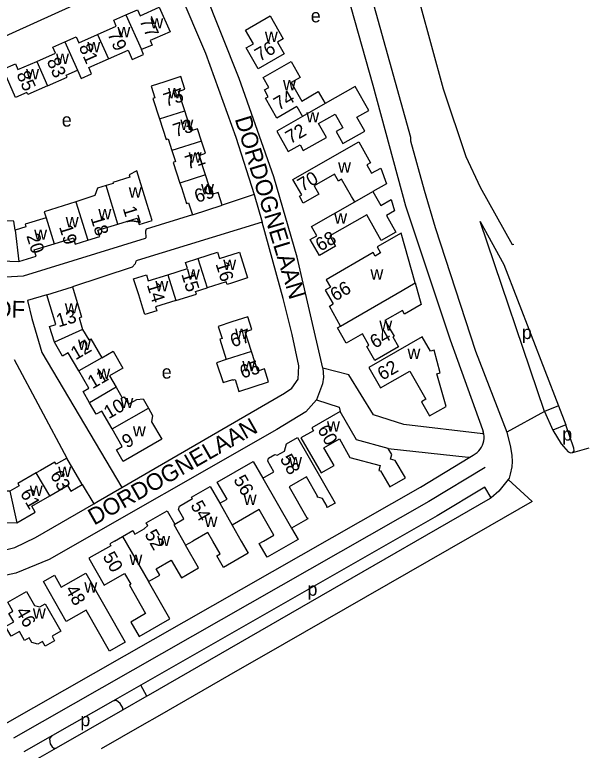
# Model space of a CAD drawing. Extents: x 157768 to 159790, y 387230 to 389604.
# Drawn here: x 159618.3 to 159790.2, y 387687.4 to 387907.4 of the extents above; entities that cross this region are included whole.
import ezdxf

# ---------------------------------------------------------------- set-up
doc = ezdxf.new("R2010")
doc.units = 0
for name, color, linetype in [('BLT_Basislijn', 7, 'Continuous'), ('BLT_Bebouwing', 7, 'Continuous'), ('BLT_Centroide', 7, 'Continuous'), ('BLT_Huisnummer', 7, 'Continuous'), ('BLT_Huisnummer_ tussenligend', 7, 'Continuous'), ('BLT_Onderverdeling_panden', 7, 'Continuous'), ('BLT_Straatnaam', 7, 'Continuous'), ('BLT_Vlakafsluiter', 7, 'Continuous')]:
    doc.layers.add(name, color=color, linetype=linetype)

msp = doc.modelspace()

# ---------------------------------------------------------------- linework, layer by layer
at = {"layer": 'BLT_Basislijn'}
for p, q in [((159689.89, 387853.69), (159680.34, 387850.45)), ((159689.89, 387853.69), (159692.33, 387845.34)), ((159692.33, 387845.34), (159654.95, 387833.88)), ((159698.63, 387822.58), (159692.33, 387845.34)), ((159776.83, 387788.74), (159757.5, 387845.57)), ((159654.54, 387833.72), (159654.31, 387832.93)), ((159654.95, 387833.88), (159654.54, 387833.72)), ((159653.42, 387831.93), (159635.54, 387825.99)), ((159654.31, 387832.93), (159653.42, 387831.93)), ((159627.9, 387823.61), (159622.13, 387821.9)), ((159701.32, 387811.81), (159698.63, 387822.58)), ((159622.13, 387821.9), (159623.39, 387816.59)), ((159623.39, 387816.59), (159626.45, 387806.4)), ((159703.31, 387802.36), (159701.32, 387811.81)), ((159626.45, 387806.4), (159650.38, 387766.04)), ((159618.18, 387804.29), (159633.89, 387774.8)), ((159703.1, 387798.44), (159703.31, 387802.36)), ((159701.25, 387795.73), (159703.1, 387798.44)), ((159650.38, 387766.04), (159699.05, 387794.25)), ((159699.05, 387794.25), (159701.25, 387795.73)), ((159780.97, 387790.46), (159783.16, 387784.76)), ((159776.83, 387788.74), (159779.26, 387783.11)), ((159783.16, 387784.76), (159779.26, 387783.11)), ((159758.37, 387782.06), (159758.63, 387781.96)), ((159758.63, 387781.96), (159758.47, 387782.64)), ((159765.55, 387782.51), (159766.67, 387778.05)), ((159730.05, 387777.68), (159753.92, 387775.06)), ((159753.92, 387775.06), (159754.42, 387775.06)), ((159754.42, 387775.06), (159755.48, 387775.7)), ((159638.49, 387766.86), (159641.92, 387761.15)), ((159655.99, 387706.92), (159647.62, 387702.15)), ((159657.83, 387703.59), (159655.99, 387706.92)), ((159647.62, 387702.15), (159629.57, 387691.87)), ((159657.83, 387703.59), (159650.54, 387699.41)), ((159650.54, 387699.41), (159630.74, 387688.08)), ((159661.61, 387697.84), (159656.3, 387694.79)), ((159656.3, 387694.79), (159644.16, 387687.83)), ((159629.57, 387691.87), (159621.02, 387687)), ((159630.74, 387688.08), (159622.98, 387683.64))]:
    msp.add_line(p, q, dxfattribs=at)
for points in [[(159692.84, 388081.49), (159706.76, 388031.4), (159708.11, 388025.69), (159746.51, 387885.2)], [(159720.03, 387930.6), (159736.67, 387870.75), (159736.74, 387869.7), (159740.78, 387854.95), (159744.13, 387843.74), (159756.15, 387806.81), (159765.55, 387782.51)], [(159713.96, 387928.53), (159716.64, 387917.56), (159725.48, 387886.3), (159735.17, 387850.25), (159748.57, 387810.22), (159758.29, 387783.31), (159758.47, 387782.64)], [(159593.73, 387893.44), (159598.42, 387893.3), (159661.18, 387921.83), (159663.45, 387921.58), (159665.84, 387918.02), (159667.43, 387914.68), (159675.33, 387895.95), (159684.44, 387870.81), (159689.89, 387853.69)], [(159710.46, 387801.68), (159702.78, 387834.9), (159695.78, 387858.95), (159685.49, 387888.37), (159674.92, 387914.97)], [(159746.51, 387885.2), (159753.28, 387864.96), (159757.5, 387855.82), (159767.09, 387838.67), (159767.58, 387838.81)], [(159671.47, 387847.59), (159657.67, 387843.31), (159657.41, 387842.64), (159657.56, 387840.64), (159657.34, 387840.48), (159620.87, 387829.25), (159606.86, 387828.46), (159591.66, 387828.05)], [(159757.5, 387845.57), (159764.67, 387832.74), (159780.97, 387790.46)], [(159710.46, 387801.68), (159710.63, 387798.96), (159710.4, 387797.04), (159708.54, 387792.2)], [(159758.37, 387782.06), (159734.73, 387784.83), (159725.65, 387787.71), (159718.29, 387799.71), (159710.46, 387801.68)], [(159708.54, 387792.2), (159705.37, 387788.65), (159696.74, 387783.35), (159628.58, 387744.46), (159618.61, 387740.41), (159614.41, 387739.52), (159607.82, 387739.2), (159553.26, 387740.56), (159549.08, 387741.46), (159546.02, 387742.49), (159541.79, 387744.82)], [(159708.54, 387792.2), (159715.35, 387789.99), (159715.66, 387788.79)], [(159780.97, 387790.46), (159776.83, 387788.74)], [(159779.26, 387783.11), (159781.76, 387779.04), (159783.92, 387776.66), (159784.71, 387776.39), (159785.23, 387776.5)], [(159785.23, 387776.5), (159785.66, 387777.02), (159785.61, 387777.82), (159783.16, 387784.76)], [(159755.48, 387775.7), (159756.07, 387776.05), (159756.62, 387776.46), (159757.12, 387776.94), (159757.56, 387777.47), (159757.93, 387778.05), (159758.24, 387778.66), (159758.47, 387779.31), (159758.63, 387779.98), (159758.7, 387780.67), (159758.7, 387781.36), (159758.63, 387781.96)], [(159766.67, 387778.05), (159767.05, 387775.62), (159767.16, 387773.83), (159766.98, 387772.21), (159766.57, 387770.01), (159766.19, 387768.82), (159765.93, 387768.36)], [(159615.48, 387695.35), (159739.66, 387766.11), (159754.42, 387775.06)], [(159759.04, 387772.01), (159742.2, 387761.8), (159617.95, 387691)], [(159765.93, 387768.36), (159763.13, 387764.95), (159760.85, 387762.94)], [(159641.92, 387761.15), (159643.24, 387761.91), (159650.38, 387766.04)], [(159760.85, 387762.94), (159758.94, 387766.11), (159744.73, 387757.49), (159655.99, 387706.92)], [(159551.98, 387748.39), (159552.96, 387748.09), (159607.94, 387746.74), (159613.77, 387746.93), (159618.29, 387748.02), (159624.54, 387751.08), (159641.92, 387761.15)], [(159760.85, 387762.94), (159760.57, 387762.7), (159709.96, 387733.64), (159658.27, 387703.84), (159657.83, 387703.59)], [(159773.14, 387761.82), (159760.43, 387754.54), (159692.81, 387715.75)], [(159692.81, 387715.75), (159684.94, 387711.23), (159661.61, 387697.84)], [(159650.54, 387699.41), (159650.67, 387699.75), (159650.61, 387700.11), (159649.89, 387701.41), (159648.71, 387702.31), (159647.62, 387702.15)], [(159629.57, 387691.87), (159628.75, 387690.88), (159628.94, 387689.36), (159629.46, 387688.47), (159630.01, 387688.02), (159630.74, 387688.08)]]:
    msp.add_lwpolyline(points, dxfattribs=at)
at = {"layer": 'BLT_Bebouwing'}
for p, q in [((159702.73, 387879.93), (159704.39, 387876.95)), ((159704.39, 387876.95), (159696.68, 387872.58)), ((159671.47, 387847.59), (159680.34, 387850.45)), ((159638.49, 387766.86), (159633.89, 387774.8)), ((159683.32, 387754.72), (159686.04, 387750)), ((159648.17, 387750), (159650.59, 387751.39)), ((159669.39, 387748.73), (159671.6, 387750))]:
    msp.add_line(p, q, dxfattribs=at)
for points in [[(159651.57, 387907.36), (159655.01, 387908.88), (159655.78, 387907.12), (159661.56, 387909.66), (159664.8, 387902.29), (159660.22, 387900.27), (159658.83, 387899.66), (159659.41, 387898.35), (159656.27, 387896.97)], [(159643.09, 387901.51), (159648.69, 387903.97), (159647.91, 387905.75), (159651.57, 387907.36)], [(159687.35, 387902.83), (159694.7, 387907.03), (159698.61, 387900.18), (159696.93, 387899.22), (159698.95, 387895.69), (159691.13, 387891.23), (159687.56, 387897.49), (159689.7, 387898.71), (159687.35, 387902.83)], [(159633.26, 387899.28), (159636.72, 387900.8), (159637.49, 387899.05), (159643.09, 387901.51)], [(159624.87, 387893.47), (159630.51, 387895.95), (159629.73, 387897.73), (159633.26, 387899.28)], [(159646.31, 387894.19), (159652.24, 387896.8), (159653.46, 387894.02), (159656.86, 387895.52), (159656.27, 387896.97)], [(159628.1, 387886.12), (159622.2, 387883.52), (159621.92, 387884.16), (159618.52, 387882.66), (159616.83, 387886.51), (159614.81, 387891.08), (159618.48, 387892.7), (159619.23, 387890.99), (159624.87, 387893.47)], [(159637.05, 387890.86), (159638.15, 387888.36), (159641.3, 387889.74), (159640.48, 387891.63), (159646.31, 387894.19)], [(159702.73, 387879.93), (159696.71, 387876.5), (159693.36, 387882.42), (159694.14, 387882.86), (159692.98, 387884.91), (159694.29, 387885.65), (159692.59, 387888.65), (159701.02, 387893.45)], [(159701.02, 387893.45), (159703.72, 387888.65), (159701.04, 387887.14), (159704.18, 387881.58)], [(159628.1, 387886.12), (159633.96, 387888.7), (159633.67, 387889.37), (159637.05, 387890.86)], [(159669.18, 387878.68), (159667.3, 387884.49), (159669.19, 387885.1), (159667.96, 387888.91), (159663.2, 387887.38), (159659.12, 387886.06), (159660.26, 387882.53), (159659.62, 387882.32), (159661.59, 387876.23)], [(159696.68, 387872.58), (159700.12, 387866.51), (159703.65, 387868.51), (159704.63, 387866.78), (159711.53, 387870.69), (159709.16, 387874.87), (159714.15, 387877.7), (159716.47, 387873.61), (159714.49, 387872.49), (159716.51, 387868.91), (159723, 387872.59), (159720.63, 387876.78), (159724.23, 387878.79), (159720.2, 387885.91), (159711.2, 387880.81)], [(159704.18, 387881.58), (159709.13, 387884.44), (159711.2, 387880.81)], [(159674.14, 387869.63), (159672.96, 387873.31), (159671.1, 387872.71), (159669.18, 387878.68)], [(159661.59, 387876.23), (159663.56, 387870.14), (159664.18, 387870.34), (159665.33, 387866.79)], [(159675.33, 387859.48), (159673.44, 387865.35), (159675.33, 387865.96), (159674.14, 387869.63)], [(159720.04, 387851.4), (159719.1, 387853.04), (159716.11, 387858.24), (159715.12, 387857.68), (159713.97, 387859.69), (159707.9, 387856.24), (159709.33, 387853.74), (159704.64, 387851.07), (159703.46, 387853.13), (159704.15, 387853.53), (159701.51, 387858.17), (159721.2, 387869.36), (159724.77, 387863.08), (159723.69, 387862.47), (159725.08, 387860.02), (159727.79, 387861.56), (159729.5, 387856.82), (159725.41, 387854.5)], [(159665.33, 387866.79), (159666.4, 387863.47), (159665.73, 387863.26), (159667.74, 387857.03)], [(159649.18, 387844.81), (159654.91, 387846.57), (159655.5, 387844.67), (159659.37, 387845.85), (159657.9, 387850.63), (159654.8, 387860.73), (159652.55, 387859.57), (159652.78, 387858.81), (159647.62, 387857.22), (159647.71, 387856.93), (159645.63, 387856.3)], [(159680.34, 387850.45), (159679.12, 387854.23), (159677.23, 387853.62), (159675.33, 387859.48)], [(159645.63, 387856.3), (159643.06, 387855.51), (159642.28, 387853.3), (159636.61, 387851.48)], [(159667.74, 387857.03), (159668.16, 387855.74), (159669.7, 387850.98), (159670.31, 387851.18), (159671.47, 387847.59)], [(159725.41, 387854.5), (159727.79, 387850.31), (159730.95, 387852.11), (159731.96, 387848.73), (159729.53, 387847.35), (159732.33, 387842.42), (159727.94, 387839.93), (159723.61, 387847.55), (159712.56, 387841.26), (159714.31, 387838.18), (159709.44, 387835.4), (159706.71, 387840.2), (159708.69, 387841.32), (159707.13, 387844.06), (159720.04, 387851.4)], [(159636.61, 387851.48), (159627.11, 387848.44), (159627.68, 387846.67)], [(159618.4, 387842.99), (159618, 387845.63), (159613.29, 387845.81), (159612.73, 387849.42), (159609.13, 387849.5), (159608.18, 387844.03), (159608.1, 387841.02), (159607.97, 387836.02), (159614.18, 387835.88), (159614.11, 387833.79), (159619.51, 387833.59)], [(159627.68, 387846.67), (159621.38, 387844.73), (159621.61, 387843.98), (159618.4, 387842.99)], [(159640.19, 387839.99), (159643.76, 387841.08), (159643.18, 387842.97), (159649.18, 387844.81)], [(159630.06, 387838.9), (159635.84, 387840.68), (159636.41, 387838.82), (159640.19, 387839.99)], [(159738.12, 387827.19), (159733.89, 387842.11), (159726.74, 387837.97), (159727.77, 387836.18), (159726.13, 387835.22), (159725.54, 387836.25), (159711.49, 387828.13), (159712.75, 387825.96), (159711.14, 387825.03), (159713.52, 387820.91)], [(159619.51, 387833.59), (159624.68, 387835.18), (159624.1, 387837.07), (159630.06, 387838.9)], [(159673.05, 387834.49), (159678.95, 387836.36), (159679.55, 387834.47), (159685.54, 387836.36), (159687.96, 387828.67), (159683.19, 387827.17), (159681.81, 387826.73), (159681.55, 387827.54), (159675.88, 387825.76)], [(159664.11, 387829.66), (159669.96, 387831.51), (159669.38, 387833.34), (159673.05, 387834.49)], [(159666.54, 387821.93), (159660.45, 387820.01), (159660.81, 387818.85), (159657.24, 387817.73), (159656.64, 387819.66), (159655.38, 387823.64), (159653.88, 387828.41), (159657.7, 387829.61), (159658.26, 387827.82), (159664.11, 387829.66)], [(159738.12, 387827.19), (159739.94, 387820.74), (159734.92, 387817.83), (159734.29, 387818.92), (159729.07, 387815.91), (159731.77, 387811.23), (159731.44, 387811.04), (159733.13, 387808.12), (159726.04, 387804.01), (159723.62, 387808.2), (159724.26, 387808.58), (159722.32, 387811.94), (159717.46, 387809.14), (159714.82, 387813.72), (159715.77, 387814.27)], [(159627.9, 387823.61), (159635.54, 387825.99)], [(159635.54, 387825.99), (159637.86, 387818.39), (159638.3, 387816.95), (159637.62, 387816.74), (159638.62, 387813.28)], [(159666.54, 387821.93), (159672.65, 387823.86), (159672.4, 387824.66), (159675.88, 387825.76)], [(159630.18, 387809.45), (159628.68, 387814.21), (159630.58, 387814.76), (159627.9, 387823.61)], [(159715.77, 387814.27), (159712.43, 387820.29), (159713.52, 387820.91)], [(159689.15, 387806.72), (159687.26, 387812.58), (159689.26, 387813.23), (159688.03, 387817.05), (159683.27, 387815.52), (159679.18, 387814.2), (159680.34, 387810.59), (159679.63, 387810.36), (159681.59, 387804.28)], [(159638.62, 387813.28), (159640.44, 387810.14), (159641.02, 387810.48), (159644.32, 387804.78)], [(159637.43, 387800.87), (159634.29, 387806.29), (159632.58, 387805.3), (159630.18, 387809.45)], [(159727.74, 387795.85), (159736.46, 387800.83), (159741.27, 387792.42), (159739.97, 387791.68), (159742.39, 387787.46), (159747.34, 387790.28), (159744.57, 387800.04), (159745.63, 387800.35), (159743.77, 387807.05), (159742.65, 387806.77), (159740.21, 387811.03), (159724.27, 387801.91), (159727.74, 387795.85)], [(159644.32, 387804.78), (159647.77, 387806.78), (159650.68, 387801.75), (159646.67, 387799.42), (159648.66, 387795.98)], [(159681.59, 387804.28), (159678.71, 387803.32), (159680.66, 387797.37), (159683.51, 387798.3), (159683.58, 387798.11), (159684.2, 387798.31), (159685.34, 387794.77), (159694.23, 387797.63), (159692.99, 387801.48), (159691.04, 387800.85), (159689.15, 387806.72)], [(159640.66, 387791.35), (159638.73, 387794.68), (159640.43, 387795.67), (159637.43, 387800.87)], [(159648.66, 387795.98), (159650.48, 387792.83), (159651.07, 387793.17), (159652.36, 387790.96), (159654.8, 387792.33), (159656.69, 387792.48), (159658.29, 387789.7)], [(159647.41, 387783.55), (159644.33, 387788.86), (159642.65, 387787.9), (159640.66, 387791.35)], [(159658.29, 387789.7), (159659.55, 387787.53), (159659.22, 387785.66), (159662.26, 387780.42), (159650.79, 387773.78), (159648.79, 387777.24), (159650.49, 387778.23), (159647.41, 387783.55)], [(159715.66, 387788.79), (159707.14, 387783.9), (159707.65, 387783), (159703.93, 387780.86), (159709.95, 387770.39), (159713.84, 387772.62), (159710.81, 387777.88), (159715.42, 387780.52), (159718.57, 387775.02), (159727.6, 387772.58), (159727.21, 387771.14), (159727.75, 387770.99), (159730.51, 387766.2), (159735.16, 387768.87), (159732.15, 387774.11), (159730.7, 387774.5), (159731.08, 387775.89), (159730.05, 387777.68)], [(159730.05, 387777.68), (159720.57, 387780.24), (159715.66, 387788.79)], [(159692.53, 387768.82), (159695.85, 387770.72), (159694.03, 387773.9), (159694.27, 387774.8), (159696.12, 387775.86), (159696.82, 387775.67), (159699, 387776.92), (159699.59, 387779.1), (159702.87, 387780.99), (159714.14, 387761.36), (159711.75, 387759.98), (159711.61, 387760.22), (159711.74, 387760.3), (159710.37, 387762.69), (159708.96, 387763.07), (159708.78, 387763.38), (159708.91, 387763.45), (159705.62, 387769.17), (159700.4, 387766.17), (159705.71, 387756.93), (159705.81, 387756.98), (159706, 387756.64), (159701.13, 387753.84)], [(159633.89, 387774.8), (159630.68, 387772.94), (159630.3, 387773.6), (159625.97, 387771.09), (159624.75, 387770.38)], [(159679.62, 387761.28), (159681.81, 387762.53), (159678.88, 387767.63), (159689.66, 387773.82), (159692.53, 387768.82)], [(159624.75, 387770.38), (159619.25, 387767.19), (159619.62, 387766.55), (159616.84, 387764.93)], [(159616.84, 387764.93), (159612.93, 387764.93), (159612.93, 387765.85), (159606.52, 387765.94), (159606.4, 387762.89), (159606.2, 387757.89), (159612.39, 387757.81), (159612.39, 387755.58), (159618.88, 387755.47)], [(159628.76, 387763.48), (159634.09, 387766.57), (159635.07, 387764.88), (159638.49, 387766.86)], [(159666.15, 387755.08), (159668.92, 387756.67), (159667.34, 387759.43), (159667.62, 387760.47), (159671.46, 387762.67), (159671.2, 387763.14), (159676.72, 387766.31), (159679.62, 387761.28)], [(159618.88, 387755.47), (159624.43, 387758.66), (159623.43, 387760.39), (159628.76, 387763.48)], [(159650.59, 387751.39), (159653.59, 387753.11), (159654.22, 387752.01), (159656.99, 387753.6), (159658.08, 387754.62), (159657.61, 387755.44), (159663.87, 387759.03), (159666.15, 387755.08)], [(159692.71, 387750), (159695.8, 387751.77), (159691.43, 387759.38), (159683.32, 387754.72)], [(159677.53, 387750), (159676.06, 387752.56), (159671.6, 387750)], [(159701.13, 387753.84), (159703.06, 387750.49), (159702.21, 387750)], [(159648.17, 387750), (159646.71, 387749.16), (159647.03, 387748.61), (159640.48, 387744.85), (159645.1, 387736.8), (159651.18, 387740.29), (159653.03, 387737.08), (159652.59, 387736.83), (159657.47, 387728.33), (159653.03, 387725.78), (159655.53, 387721.44), (159664.74, 387726.74), (159658.34, 387737.88)], [(159686.04, 387750), (159688.13, 387746.36), (159680.74, 387742.11), (159678.73, 387745.6), (159679.73, 387746.17), (159677.53, 387750)], [(159702.21, 387750), (159693.8, 387745.17), (159691.44, 387749.27), (159692.71, 387750)], [(159658.34, 387737.88), (159661.73, 387739.83), (159660.66, 387741.69), (159665.15, 387744.28), (159668.18, 387739.01), (159673.28, 387741.94), (159669.39, 387748.73)], [(159639.62, 387740.41), (159651.38, 387719.77), (159646.66, 387717.09), (159639.67, 387729.37), (159633.66, 387725.94), (159626.88, 387737.85), (159630.21, 387739.75), (159632.23, 387736.2), (159639.62, 387740.41)], [(159627.43, 387731.21), (159632.09, 387723.05), (159629.45, 387721.55), (159630.23, 387720.18), (159627.41, 387718.57), (159626.64, 387719.92), (159625.25, 387719.13), (159623.38, 387719.64), (159622.57, 387721.06), (159621.22, 387720.29), (159619.73, 387722.91), (159617.24, 387721.5), (159615.58, 387724.41), (159618.01, 387725.8), (159616.55, 387728.37), (159617.76, 387729.06), (159616.23, 387731.75), (159621.8, 387734.93), (159624.19, 387730.75), (159625.84, 387730.3), (159627.43, 387731.21)]]:
    msp.add_lwpolyline(points, dxfattribs=at)
at = {"layer": 'BLT_Onderverdeling_panden'}
for p, q in [((159651.57, 387907.36), (159656.27, 387896.97)), ((159643.09, 387901.51), (159646.31, 387894.19)), ((159633.26, 387899.28), (159637.05, 387890.86)), ((159624.87, 387893.47), (159628.1, 387886.12)), ((159711.2, 387880.81), (159704.39, 387876.95)), ((159661.59, 387876.23), (159669.18, 387878.68)), ((159674.14, 387869.63), (159665.33, 387866.79)), ((159675.33, 387859.48), (159667.74, 387857.03)), ((159649.18, 387844.81), (159645.63, 387856.3)), ((159720.04, 387851.4), (159725.41, 387854.5)), ((159636.61, 387851.48), (159640.19, 387839.99)), ((159627.68, 387846.67), (159630.06, 387838.9)), ((159618.4, 387842.99), (159619.51, 387833.59)), ((159673.05, 387834.49), (159675.88, 387825.76)), ((159664.11, 387829.66), (159666.54, 387821.93)), ((159734.22, 387824.93), (159738.12, 387827.19)), ((159715.77, 387814.27), (159734.22, 387824.93)), ((159638.62, 387813.28), (159630.18, 387809.45)), ((159689.15, 387806.72), (159681.59, 387804.28)), ((159644.32, 387804.78), (159637.43, 387800.87)), ((159648.66, 387795.98), (159640.66, 387791.35)), ((159647.41, 387783.55), (159658.29, 387789.7)), ((159628.76, 387763.48), (159624.75, 387770.38)), ((159692.53, 387768.82), (159701.13, 387753.84)), ((159616.84, 387764.93), (159618.88, 387755.47)), ((159679.62, 387761.28), (159683.32, 387754.72)), ((159650.59, 387751.39), (159658.34, 387737.88))]:
    msp.add_line(p, q, dxfattribs=at)
msp.add_lwpolyline([(159666.15, 387755.08), (159665.86, 387754.91), (159669.39, 387748.73)], dxfattribs=at)
at = {"layer": 'BLT_Vlakafsluiter'}
for p, q in [((159776.83, 387788.74), (159765.55, 387782.51)), ((159785.23, 387776.5), (159790.2, 387777.83)), ((159773.14, 387761.82), (159765.93, 387768.36))]:
    msp.add_line(p, q, dxfattribs=at)

# ---------------------------------------------------------------- texts
at = {"layer": 'BLT_Centroide'}
for s, p in [('e', (159706.87, 387905.13)), ('w', (159658.88, 387903.31)), ('w', (159649.02, 387900.69)), ('w', (159693.14, 387899.27)), ('w', (159640.02, 387896.16)), ('w', (159630.66, 387892.69)), ('w', (159621.7, 387888.06)), ('w', (159698.56, 387884.81)), ('w', (159664.16, 387882.38)), ('w', (159705.52, 387875.19)), ('e', (159632.38, 387873.95)), ('w', (159667.86, 387872.92)), ('w', (159670.33, 387863.14)), ('w', (159715.04, 387860.22)), ('w', (159652.42, 387852.72)), ('w', (159674.05, 387853.73)), ('w', (159643.33, 387846.19)), ('w', (159633.55, 387843.81)), ('w', (159713.88, 387844.94)), ('w', (159624.11, 387840.09)), ('w', (159680.68, 387831.06)), ('w', (159669.82, 387828.22)), ('w', (159724.71, 387828.19)), ('w', (159660.38, 387824.66)), ('w', (159633.27, 387818.06)), ('w', (159727.38, 387812.88)), ('w', (159684.22, 387810.47)), ('p', (159770.04, 387810.41)), ('w', (159637.23, 387807.16)), ('w', (159735.8, 387804.48)), ('w', (159686.39, 387800.75)), ('w', (159643, 387798.5)), ('e', (159662.28, 387798.58)), ('w', (159649.91, 387789.75)), ('w', (159711.72, 387782.69)), ('w', (159653.66, 387781.27)), ('p', (159782.1, 387780.03)), ('w', (159700.38, 387772.06)), ('w', (159631.32, 387769.12)), ('w', (159622.8, 387763.48)), ('w', (159686.79, 387760.76)), ('w', (159675.09, 387754.22)), ('w', (159660.91, 387748.47)), ('w', (159652.61, 387742.84)), ('w', (159639.12, 387734.59)), ('p', (159705.88, 387733.64)), ('w', (159623.73, 387726.75)), ('p', (159637.93, 387694.61))]:
    msp.add_text(s, height=4, dxfattribs=at).set_placement(p)
at = {"layer": 'BLT_Huisnummer'}
for s, rotation, p in [('77', 293.7435, (159655.55, 387905.64)), ('76', 30.0317, (159691.58, 387893.3)), ('81', 293.7435, (159637.39, 387897.81)), ('85', 293.7435, (159618.74, 387889.61)), ('75', 17.8827, (159663.55, 387879.85)), ('74', 30.0317, (159697.25, 387878.67)), ('72', 30.0317, (159700.76, 387868.64)), ('70', 30.0317, (159704.35, 387854.4)), ('69', 17.8847, (159672.81, 387851.1)), ('17', 287.0724, (159650.58, 387849.51)), ('18', 287.0724, (159640.96, 387846.64)), ('19', 287.0724, (159631.54, 387843.97)), ('68', 30.0317, (159709.74, 387836.5)), ('20', 287.0724, (159621.74, 387841.3)), ('16', 287.485, (159678.35, 387832.89)), ('15', 287.485, (159668.08, 387829.84)), ('14', 287.485, (159657.78, 387826.62)), ('66', 30.0317, (159714.15, 387821.57)), ('13', 16.1165, (159631.38, 387813.9)), ('67', 17.8442, (159683.51, 387807.89)), ('64', 29.7541, (159726.01, 387807.46)), ('12', 30.0525, (159636.51, 387804.02)), ('65', 17.8412, (159686.4, 387798.53)), ('62', 29.7541, (159728.26, 387797.92)), ('11', 30.0525, (159641.57, 387795.38)), ('10', 30.0525, (159646.4, 387786.39)), ('60', 299.8663, (159708.71, 387783.37)), ('9', 30.0525, (159651.83, 387777.62)), ('58', 299.8663, (159697.52, 387774.58)), ('63', 300.1009, (159628.75, 387769.74)), ('56', 299.8663, (159683.61, 387768.35)), ('61', 300.1009, (159619.79, 387764.27)), ('54', 299.8663, (159670.76, 387760.69)), ('52', 299.8663, (159657.02, 387752.04)), ('50', 299.6619, (159644.49, 387745.41)), ('48', 299.6619, (159633.31, 387735.48)), ('46', 299.6619, (159618.44, 387728.93))]:
    msp.add_text(s, height=4, rotation=rotation, dxfattribs=at).set_placement(p)
at = {"layer": 'BLT_Huisnummer_ tussenligend'}
for s, rotation, p in [('79', 293.7435, (159645.97, 387901.64)), ('83', 293.7435, (159627.79, 387893.59)), ('73', 17.8847, (159666.42, 387870.76)), ('71', 17.8847, (159670.05, 387861.14))]:
    msp.add_text(s, height=4, rotation=rotation, dxfattribs=at).set_placement(p)
at = {"layer": 'BLT_Straatnaam'}
for s, height, rotation, p in [('DORDOGNELAAN', 5, 286.9302, (159684.09, 387876.28)), ('PICARDIEHOF', 4.9999, 358.8635, (159575.71, 387817.69)), ('DORDOGNELAAN', 5, 29.7066, (159642.05, 387754.58))]:
    msp.add_text(s, height=height, rotation=rotation, dxfattribs=at).set_placement(p)

doc.saveas('drawing.dxf')
